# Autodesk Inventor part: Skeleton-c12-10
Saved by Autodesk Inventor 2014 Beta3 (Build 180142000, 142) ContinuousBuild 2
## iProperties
Created: 2011-01
Part Number: Skeleton-c12-10
Material: Generic
Document SubType Name: Modeling
Designer: Thom Tremblay
Density: 1 g/cm^3
Appearance: Generic
_SkeletonDoc: Frame Skeleton File
_Version: 15.0.0
Author: Thom Tremblay
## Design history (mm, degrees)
sketch "Reference Skeleton"
  geometry: L1 through (404.523, 1164.395) direction (1, 0); L2 through (325.691, 1070.446) direction (1, 0); 34 other entities
  constraints: 10 horizontal
